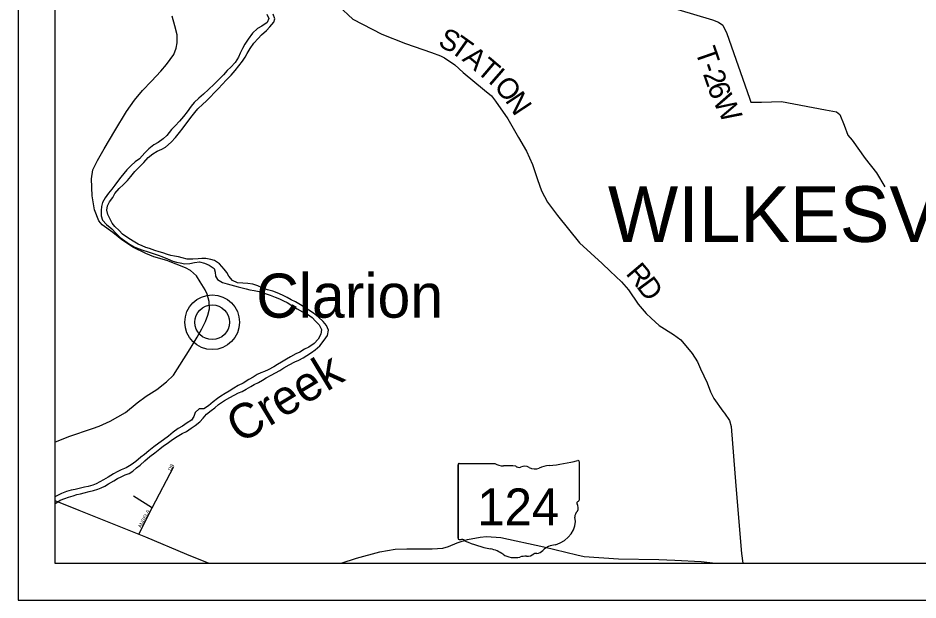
# Model space of a CAD drawing. Extents: x -15 to 405, y -40 to 87.
# Drawn here: x 23.065 to 25.513, y -34.096 to -32.512 of the extents above; entities that cross this region are included whole.
import ezdxf

# ---------------------------------------------------------------- set-up
doc = ezdxf.new("R2010")
doc.units = 0
for name, color, linetype in [('GM_P_State_Location', 7, 'Continuous'), ('GM_X_County_Road_Text', 7, 'Continuous'), ('GM_X_Major_Lake', 7, 'Continuous'), ('GM_X_Major_River', 7, 'Continuous'), ('GM_X_Minor_Lake', 7, 'Continuous'), ('GM_X_Minor_River', 7, 'Continuous'), ('GM_X_State_Location', 7, 'Continuous'), ('GM_X_Township', 7, 'Continuous'), ('GM_X_Township_Road', 7, 'Continuous'), ('GM_X_Township_Road_Text', 7, 'Continuous'), ('GM_X_Township_ROW', 7, 'Continuous'), ('GM_X_Township_Subdivision', 7, 'Continuous'), ('GM_X_Township_Subdivision_Text', 7, 'Continuous'), ('GM_X_Township_Text', 7, 'Continuous')]:
    doc.layers.add(name, color=color, linetype=linetype)

msp = doc.modelspace()

# ---------------------------------------------------------------- linework, layer by layer
at = {"layer": 'GM_P_State_Location'}
for points in [[(23.1652, -33.666), (23.2037, -33.651), (23.2674, -33.6293), (23.2859, -33.6226), (23.3155, -33.6087), (23.358, -33.5855), (23.3891, -33.5595), (23.4142, -33.5411), (23.4427, -33.523), (23.4692, -33.5023), (23.4882, -33.4839), (23.5336, -33.4117), (23.5527, -33.3804), (23.5652, -33.3577), (23.5752, -33.3377), (23.5813, -33.3203), (23.5859, -33.3029), (23.5849, -33.2835), (23.5797, -33.2638), (23.5741, -33.2512), (23.5606, -33.2296), (23.5504, -33.2132), (23.5342, -33.1991), (23.5206, -33.1922), (23.4704, -33.1722), (23.4345, -33.1621), (23.4126, -33.1525), (23.3794, -33.1368), (23.3477, -33.1154), (23.3232, -33.0959), (23.2938, -33.0749), (23.2848, -33.0639), (23.2732, -33.0339), (23.2666, -32.9963), (23.2649, -32.9493), (23.2684, -32.9255), (23.281, -32.9001), (23.2993, -32.8684), (23.3283, -32.8193), (23.3603, -32.7668), (23.3817, -32.7358), (23.4037, -32.7094), (23.4284, -32.6838), (23.4535, -32.657), (23.4691, -32.6381), (23.4886, -32.6113), (23.4954, -32.5943), (23.4982, -32.5799), (23.4979, -32.5575), (23.492, -32.5332), (23.4845, -32.5074)], [(24.8599, -32.4886), (24.9539, -32.5167), (24.9705, -32.5232), (24.9827, -32.5319), (24.9933, -32.5543), (25.0546, -32.7301), (25.0584, -32.7407), (25.0583, -32.7406), (25.0872, -32.7411), (25.1422, -32.7393), (25.2612, -32.7621), (25.2911, -32.7671), (25.3006, -32.7743), (25.3127, -32.8039), (25.3222, -32.8309), (25.3343, -32.8442), (25.3695, -32.8947), (25.4002, -32.9334), (25.4226, -32.971)]]:
    msp.add_lwpolyline(points, dxfattribs=at)
at = {"layer": 'GM_X_Major_River'}
for points in [[(23.3938, -33.9163), (23.4301, -33.8446), (23.489, -33.7321)], [(23.4285, -33.8436), (23.3792, -33.8126)]]:
    msp.add_lwpolyline(points, dxfattribs=at)
at = {"layer": 'GM_X_State_Location'}
for points in [[(23.1652, -33.8251), (23.2302, -33.851), (23.3255, -33.8888), (23.3938, -33.9163), (23.4118, -33.9236), (23.5231, -33.9705), (23.5841, -33.9955)], [(23.9443, -33.9955), (23.9856, -33.9817), (24.049, -33.9646), (24.0913, -33.9573), (24.1228, -33.9562), (24.1919, -33.9561), (24.2204, -33.9543), (24.2365, -33.9503), (24.2598, -33.9404), (24.288, -33.931), (24.3219, -33.9243), (24.3398, -33.9227), (24.3785, -33.9255), (24.495, -33.9512), (24.5851, -33.9727), (24.6051, -33.9768), (24.6984, -33.9835), (24.8082, -33.9852), (24.8518, -33.987), (24.9235, -33.9911), (24.9623, -33.9955)]]:
    msp.add_lwpolyline(points, dxfattribs=at)
at = {"layer": 'GM_X_Township'}
for p, q in [((23.0652, -27.0955), (23.0652, -34.0955)), ((23.1652, -27.1955), (23.1652, -33.9955)), ((23.1652, -33.9955), (29.9652, -33.9955)), ((23.0652, -34.0955), (30.0652, -34.0955))]:
    msp.add_line(p, q, dxfattribs=at)
at = {"layer": 'GM_X_Township_Road'}
for points in [[(23.7424, -32.5013), (23.7472, -32.5138), (23.7433, -32.524), (23.7288, -32.5342), (23.7166, -32.5409), (23.7033, -32.5537), (23.6914, -32.5695), (23.6822, -32.5831), (23.676, -32.5948), (23.6699, -32.6077), (23.6645, -32.619), (23.6556, -32.6334), (23.6438, -32.6454), (23.6342, -32.6552), (23.6243, -32.6669), (23.6109, -32.6805), (23.5986, -32.6925), (23.5834, -32.7065), (23.57, -32.7193), (23.5574, -32.7298), (23.5448, -32.7418), (23.536, -32.7516), (23.5256, -32.7671), (23.5149, -32.7799), (23.5042, -32.7928), (23.4931, -32.8052), (23.4831, -32.8158), (23.4697, -32.832), (23.4602, -32.8406), (23.4468, -32.8504), (23.4346, -32.8575), (23.4213, -32.868), (23.4098, -32.8793), (23.3956, -32.8948), (23.3838, -32.9034), (23.3731, -32.9132), (23.3613, -32.9253), (23.3452, -32.9449), (23.336, -32.9573), (23.3283, -32.9671), (23.3207, -32.9781), (23.3115, -32.989), (23.3026, -33.0015), (23.2953, -33.0143), (23.2922, -33.0245), (23.291, -33.0355), (23.2913, -33.0503), (23.2946, -33.0625)], [(23.3066, -33.0353), (23.3086, -33.0228), (23.3143, -33.0118), (23.3231, -33.0001), (23.3289, -32.9899), (23.3408, -32.9763), (23.3522, -32.9647), (23.363, -32.9537), (23.3718, -32.9432), (23.3832, -32.93), (23.3947, -32.9179), (23.407, -32.9051), (23.4192, -32.8919), (23.4318, -32.8814), (23.444, -32.8747), (23.4562, -32.8687), (23.4668, -32.8631), (23.4817, -32.8499), (23.4936, -32.8371), (23.5047, -32.8235), (23.5147, -32.8111), (23.5354, -32.7831), (23.5461, -32.7692), (23.5541, -32.7594), (23.5675, -32.7469), (23.577, -32.7387), (23.5889, -32.7262), (23.5988, -32.7157), (23.6103, -32.704), (23.6206, -32.6931), (23.6325, -32.6803), (23.6447, -32.6678), (23.6555, -32.655), (23.6658, -32.6418), (23.6761, -32.6294), (23.6827, -32.6188), (23.6884, -32.609), (23.6969, -32.5954), (23.7065, -32.5807), (23.718, -32.5682), (23.7275, -32.558), (23.7413, -32.5464), (23.7504, -32.5362), (23.7608, -32.5238), (23.7639, -32.5139), (23.7594, -32.5018)], [(23.3672, -33.7511), (23.3775, -33.7451), (23.3874, -33.7357), (23.3974, -33.7282), (23.4104, -33.7165), (23.4241, -33.7049), (23.4378, -33.6947), (23.4508, -33.6846), (23.4611, -33.6763), (23.4707, -33.6696), (23.4852, -33.6587), (23.4985, -33.6504), (23.5118, -33.6425), (23.5236, -33.6369), (23.5366, -33.6283), (23.5469, -33.6208), (23.5599, -33.6103), (23.5691, -33.6005), (23.5779, -33.5899), (23.5908, -33.5798), (23.6004, -33.5726), (23.6103, -33.564), (23.6267, -33.5531), (23.6412, -33.5441), (23.6534, -33.5385), (23.6652, -33.5321), (23.6751, -33.528), (23.6858, -33.5216), (23.6983, -33.5149), (23.7079, -33.5089), (23.7189, -33.5033), (23.73, -33.4973), (23.7399, -33.4913), (23.7536, -33.4838), (23.7654, -33.4771), (23.7776, -33.4711), (23.7886, -33.464), (23.8027, -33.4557), (23.818, -33.4479), (23.8286, -33.4426), (23.8412, -33.4363), (23.8507, -33.4307), (23.8637, -33.4224), (23.8732, -33.4153), (23.8862, -33.4036), (23.8981, -33.3885), (23.9073, -33.3757), (23.9101, -33.3613), (23.9041, -33.3491), (23.8951, -33.3377), (23.8823, -33.3262), (23.8691, -33.3151), (23.8566, -33.3067), (23.8434, -33.2986), (23.8336, -33.2928), (23.8196, -33.284), (23.8086, -33.2786), (23.7977, -33.2728), (23.7848, -33.2663), (23.7704, -33.2598), (23.758, -33.2551), (23.7439, -33.2512), (23.7296, -33.2466), (23.7175, -33.2404), (23.7035, -33.2361), (23.6906, -33.2341), (23.6769, -33.2333), (23.6625, -33.2324), (23.6485, -33.2266), (23.6387, -33.2148), (23.6331, -33.2049), (23.626, -33.195), (23.6132, -33.1805), (23.6, -33.1717), (23.5901, -33.1689), (23.5757, -33.1662), (23.5651, -33.1661), (23.5556, -33.1672), (23.5404, -33.1686), (23.5249, -33.1681), (23.5116, -33.165), (23.5014, -33.1622), (23.4912, -33.1603), (23.4813, -33.1583), (23.4715, -33.1556), (23.459, -33.1513), (23.4491, -33.1478), (23.437, -33.1443), (23.423, -33.1389), (23.4132, -33.1362), (23.4026, -33.1315), (23.392, -33.1277), (23.378, -33.1192), (23.3637, -33.1104), (23.3497, -33.1004), (23.3403, -33.0905), (23.329, -33.0794), (23.3211, -33.0699), (23.3144, -33.0558), (23.3099, -33.0463), (23.3066, -33.0353)], [(23.2946, -33.0625), (23.3063, -33.0736), (23.3202, -33.0858), (23.3311, -33.0976), (23.3428, -33.1091), (23.3557, -33.1183), (23.3685, -33.1275), (23.3828, -33.1352), (23.3949, -33.1402), (23.4048, -33.1441), (23.4192, -33.1484), (23.4328, -33.153), (23.446, -33.1573), (23.4563, -33.1611), (23.4714, -33.1669), (23.4861, -33.1735), (23.4967, -33.1762), (23.5062, -33.1778), (23.5191, -33.1813), (23.5324, -33.1803), (23.5449, -33.177), (23.5586, -33.1752), (23.5722, -33.179), (23.5851, -33.1848), (23.5983, -33.1936), (23.6013, -33.2039), (23.6027, -33.2142), (23.6076, -33.2237), (23.6212, -33.2317), (23.634, -33.2353), (23.6439, -33.238), (23.6545, -33.2403), (23.6643, -33.2431), (23.6753, -33.2466), (23.6859, -33.2489), (23.6958, -33.2513), (23.7071, -33.2532), (23.7208, -33.2564), (23.7306, -33.2591), (23.7404, -33.2626), (23.751, -33.2661), (23.765, -33.2715), (23.7768, -33.2757), (23.7877, -33.2815), (23.7976, -33.2861), (23.8104, -33.2946), (23.8248, -33.303), (23.8387, -33.3111), (23.8523, -33.3176), (23.8652, -33.3268), (23.8742, -33.3367), (23.884, -33.3471), (23.8907, -33.3596), (23.8891, -33.3725), (23.8818, -33.3857), (23.8707, -33.3974), (23.8562, -33.4076), (23.844, -33.4132), (23.8315, -33.421), (23.8212, -33.4259), (23.8063, -33.4341), (23.7953, -33.4405), (23.7819, -33.4487), (23.7713, -33.4547), (23.7606, -33.4611), (23.7457, -33.469), (23.7358, -33.4738), (23.7256, -33.4776), (23.716, -33.482), (23.7046, -33.4892), (23.6932, -33.4955), (23.6779, -33.5053), (23.6642, -33.512), (23.652, -33.5191), (23.6398, -33.527), (23.6284, -33.5341), (23.6173, -33.5409), (23.6074, -33.5473), (23.596, -33.5567), (23.5834, -33.5676), (23.5704, -33.5758), (23.5575, -33.5757), (23.5468, -33.5851), (23.5433, -33.5961), (23.5375, -33.6063), (23.525, -33.6134), (23.5124, -33.6221), (23.5006, -33.6292), (23.4876, -33.6389), (23.4742, -33.6502), (23.4605, -33.66), (23.4483, -33.669), (23.4345, -33.6784), (23.4212, -33.6897), (23.4093, -33.6998), (23.3994, -33.7073), (23.3853, -33.719), (23.3727, -33.7276), (23.359, -33.7355), (23.346, -33.7411), (23.3346, -33.7467)], [(23.3346, -33.7467), (23.3247, -33.7523), (23.3106, -33.7609), (23.2977, -33.7684), (23.2877, -33.7744), (23.2778, -33.7793), (23.2683, -33.7834), (23.2558, -33.7863), (23.2459, -33.7886), (23.2349, -33.7915), (23.2204, -33.7948), (23.2102, -33.797), (23.1972, -33.8003), (23.1835, -33.8056), (23.171, -33.8119), (23.1652, -33.815)], [(23.1652, -33.8334), (23.1796, -33.8241), (23.1922, -33.8189), (23.2021, -33.8159), (23.2154, -33.8118), (23.2256, -33.8089), (23.2355, -33.8063), (23.2454, -33.8037), (23.2587, -33.8), (23.2701, -33.7975), (23.2823, -33.7937), (23.2918, -33.79), (23.3017, -33.7855), (23.3112, -33.7792), (23.3261, -33.7709), (23.3356, -33.7649), (23.3455, -33.7601), (23.3566, -33.7552), (23.3672, -33.7511)]]:
    msp.add_lwpolyline(points, dxfattribs=at)
at = {"layer": 'GM_X_Township_Subdivision'}
for p, q in [((24.262, -33.7276), (24.262, -33.9277)), ((24.262, -33.9277), (24.262, -33.7276)), ((24.262, -33.9277), (24.262, -33.7276)), ((24.2653, -33.7241), (24.3618, -33.7241)), ((24.5916, -33.7192), (24.5916, -33.8239)), ((24.5916, -33.8238), (24.5916, -33.8239))]:
    msp.add_line(p, q, dxfattribs=at)
for centre, major_axis, start_param, end_param in [((24.2658, -33.7271), (0.00382, 0), 1.712693, 3.28349), ((24.3848, -33.7009), (0.037, 0), 4.042523, 4.731795), ((24.3971, -33.8365), (0.133, 0), 1.404758, 1.657858), ((24.4273, -33.7261), (0.0107, 0), 3.836095, 5.185415), ((24.4429, -33.7492), (0.0222, 0), 0.950623, 2.079405), ((24.5188, -33.7852), (0.0703, 0), 1.699011, 2.107814), ((24.4742, -33.4513), (0.3495, 0), 4.814394, 5.042369), ((24.588, -33.7187), (0.00367, 0), 6.141152, 7.989035), ((24.4716, -33.7175), (0.0267, 0), 4.081561, 5.145723), ((24.5908, -33.8315), (0.00568, 0), 1.883978, 3.671073), ((24.5877, -33.8243), (0.00393, 0), 5.05454, 6.418171), ((24.6048, -33.8677), (0.0248, 0), 2.387724, 3.262537), ((24.5547, -33.8448), (0.0341, 0), 5.934695, 6.695948), ((24.4938, -33.881), (0.0874, 0), 5.101752, 6.440018), ((24.2659, -33.9281), (0.00385, 0), 3.00124, 4.508301), ((24.2664, -33.9077), (0.0294, 0), 4.665946, 4.897461), ((24.2725, -33.9392), (0.0106, 0), 0.519207, 1.627899), ((24.4063, -33.7594), (0.2524, 0), 4.195997, 4.488961), ((24.5307, -33.9839), (0.0479, 0), 1.647645, 2.488434), ((24.331, -34.0176), (0.079, 0), 0.823519, 1.323587), ((24.4164, -33.9402), (0.0501, 0), 4.026481, 4.996735), ((24.4454, -34.0094), (0.0412, 0), 1.495662, 1.94098), ((24.4491, -33.9552), (0.0267, 0), 4.691044, 5.507374), ((24.4732, -33.9746), (0.00752, 0), 1.147584, 2.315152), ((24.47, -33.9471), (0.0282, 0), 4.937069, 5.64225)]:
    msp.add_ellipse(centre, major_axis=major_axis, ratio=0.8, start_param=start_param, end_param=end_param, dxfattribs=at)
at = {"layer": 'GM_X_Township_Subdivision_Text'}
for radius in [0.0744, 0.0472]:
    msp.add_circle((23.5934, -33.3399), radius, dxfattribs=at)
at = {"layer": 'GM_X_Township_Text'}
for points in [[(23.9367, -32.4785), (23.9755, -32.5155), (24.055, -32.5558), (24.1194, -32.5816), (24.1903, -32.6056), (24.2142, -32.6147), (24.2252, -32.6204), (24.2536, -32.6398), (24.2763, -32.6607), (24.3339, -32.7086), (24.3529, -32.7237), (24.3639, -32.7382), (24.3972, -32.7868), (24.4267, -32.8369), (24.448, -32.8745), (24.4646, -32.9106), (24.4782, -32.9515), (24.4892, -32.9827), (24.5055, -33.0134), (24.5328, -33.0491), (24.5926, -33.1235), (24.654, -33.1798), (24.676, -33.201), (24.7071, -33.2303), (24.726, -33.2519), (24.7518, -33.2907), (24.7741, -33.3157), (24.787, -33.3283), (24.8094, -33.3484), (24.848, -33.3731), (24.8685, -33.3879), (24.8992, -33.4247), (24.9136, -33.4479), (24.9215, -33.4661), (24.9393, -33.5048), (24.9491, -33.5295), (24.9575, -33.5477), (24.9824, -33.5818)], [(24.9824, -33.5818), (24.9826, -33.582), (24.9866, -33.5876), (25.0007, -33.6073), (25.0052, -33.6233), (25.0176, -33.7846), (25.0334, -33.969), (25.0369, -33.9955)]]:
    msp.add_lwpolyline(points, dxfattribs=at)

# ---------------------------------------------------------------- texts
at = {"layer": 'GM_X_County_Road_Text'}
msp.add_text('WILKESVILLE', height=0.151515, rotation=0, dxfattribs=at).set_placement((24.6697, -33.1212))
at = {"layer": 'GM_X_Major_Lake'}
for s, rotation, p in [('DR', 63.4295, (23.4813, -33.7446)), ('ANGELA', 62.9859, (23.3996, -33.9004))]:
    msp.add_text(s, height=0.00947, rotation=rotation, dxfattribs=at).set_placement(p)
at = {"layer": 'GM_X_Minor_Lake'}
for s, rotation, p in [('S', 334.574, (24.2049, -32.5874)), ('T', 324.6148, (24.2373, -32.6025)), ('A', 320.1123, (24.271, -32.6264)), ('T', 319.6446, (24.3093, -32.6584)), ('I', 319.0109, (24.3416, -32.6858)), ('O', 309.792, (24.3575, -32.6994)), ('N', 303.5203, (24.3885, -32.7365)), ('R', 310.3168, (24.7162, -33.2082)), ('D', 306.3643, (24.7458, -33.243))]:
    msp.add_text(s, height=0.0568, rotation=rotation, dxfattribs=at).set_placement(p)
at = {"layer": 'GM_X_Minor_River'}
for s, rotation, p in [('T', 289.1058, (24.9063, -32.6018)), ('2', 289.1126, (24.9278, -32.664)), ('-', 289.1014, (24.9202, -32.6419)), ('6', 289.5855, (24.9394, -32.6976)), ('W', 296.2744, (24.954, -32.7372))]:
    msp.add_text(s, height=0.0568, rotation=rotation, dxfattribs=at).set_placement(p)
at = {"layer": 'GM_X_Township_Road_Text'}
msp.add_text('Creek', height=0.0947, rotation=31.1882, dxfattribs=at).set_placement((23.6696, -33.6719))
at = {"layer": 'GM_X_Township_ROW'}
msp.add_text('Clarion', height=0.12, rotation=0, dxfattribs=at).set_placement((23.7132, -33.3274))
at = {"layer": 'GM_X_Township_Subdivision'}
msp.add_text('124', height=0.1, dxfattribs=at).set_placement((24.3143, -33.892))

doc.saveas('drawing.dxf')
